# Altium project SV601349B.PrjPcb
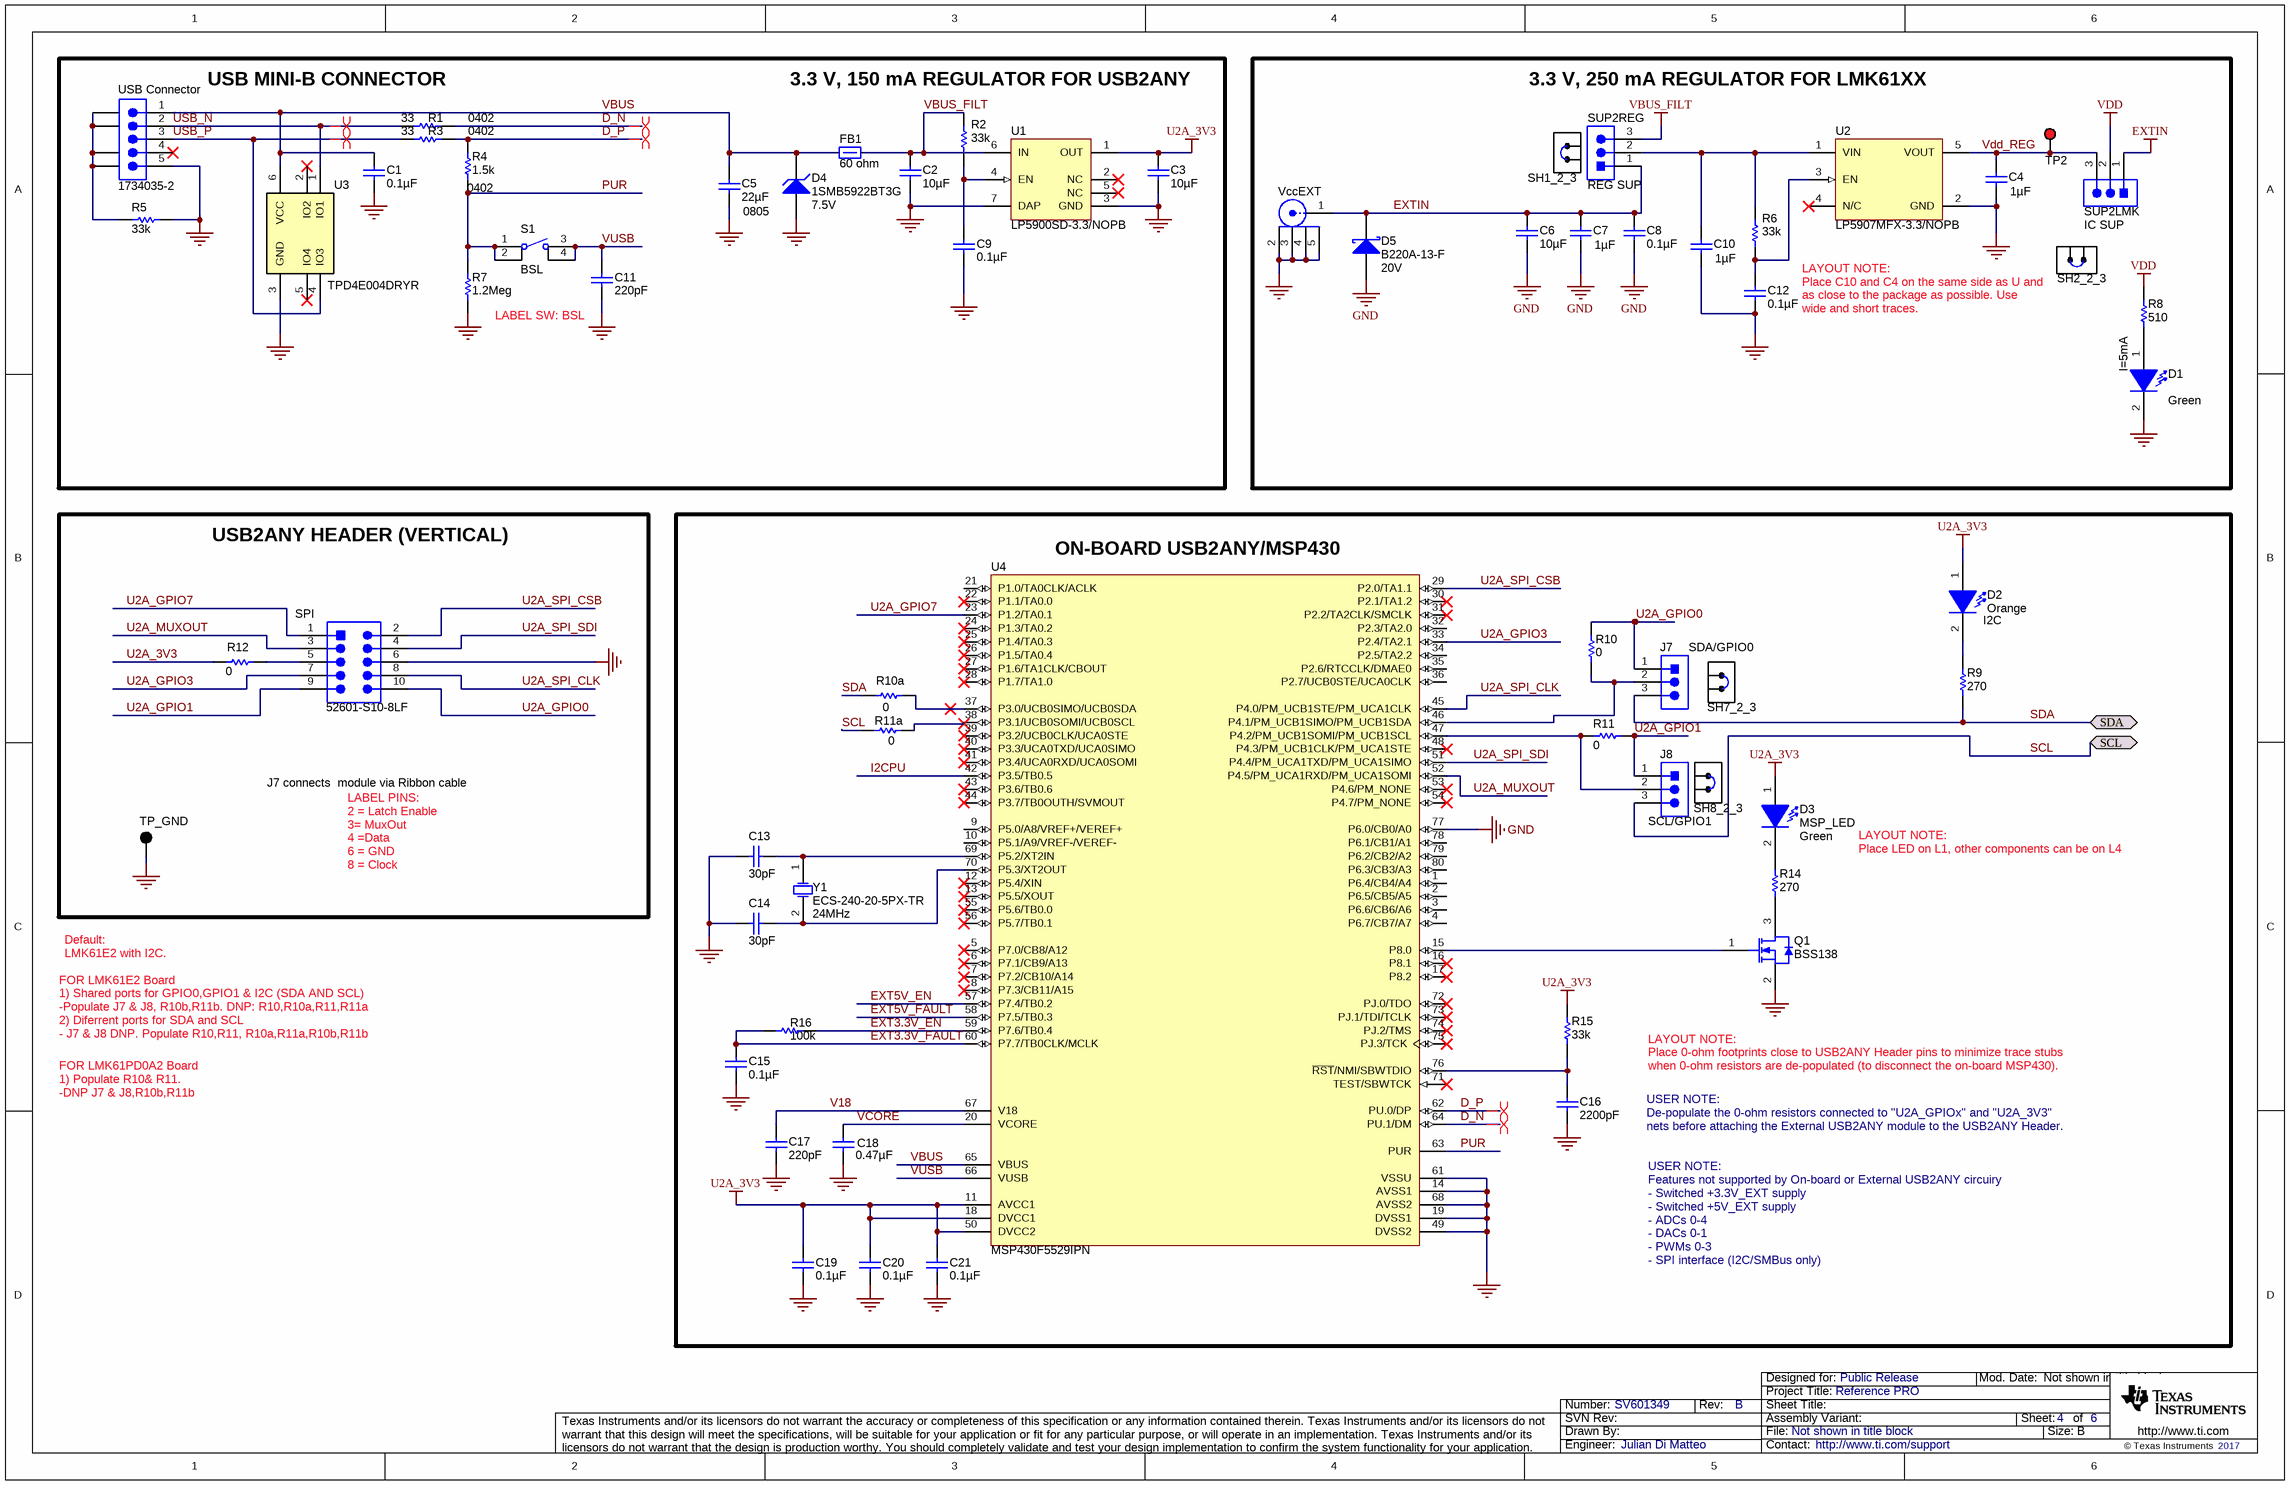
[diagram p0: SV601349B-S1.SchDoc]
CopyrightYear: 2017; PCB_Layout: Julian Di Matteo; PCB_Rev: B; PRJ_Customer: Public Release; PRJ_Engineer: Julian Di Matteo; PRJ_Number: SV601349; PRJ_Title: Reference PRO; SCH_Rev: B; TechSupport: http://www.ti.com/support; TID: N/A
3 sheets, 124 parts. Net scope: flat (ports and power ports of the same name join across sheets).
Board file: SV601349B.PcbDoc
Sheets:
  SV601349B-S1.SchDoc
  SV601349B-S2.SchDoc
  SV601349B-S3.SchDoc

## Sheet SV601349B-S1.SchDoc
size 431 x 279 mm; Date: Not shown in title block; ApprovedBy: Not shown in title block; CheckedBy: Not shown in title block; Author: Julian Di Matteo; CompanyName: Not shown in title block; Engineer: Not shown in title block; Organization: Not shown in title block; Address1: Not shown in title block; Address2: Not shown in title block; Address3: Not shown in title block; Address4: Not shown in title block; DocumentNumber: 4; Revision: Use project parameter SCH_Rev; SheetNumber: 4; SheetTotal: 6; PageSetup: Record=PageOptions¦CenterHorizontal=True¦CenterVertical=True¦PrintScale=0.90¦XCorrection=1.00¦YCorrection=1.00¦PrintKind=0¦BorderSize=5000000¦LeftOffset=0¦BottomOffset=0¦Orientation=2¦PaperLength=1000¦PaperWidth=1000¦Scale=100¦PaperSource=15¦PrintQuality=600¦MediaType=1¦DitherType=10¦PaperKind=Letter (8.5 x 11")¦PrintScaleMode=1; SheetTitle: USB2ANY / Power

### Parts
C1  ValueDisplayed: 0.1µF  [0603]  (hidden comment: C0603C104J4RACTU)
C2  ValueDisplayed: 10µF  [0603]  (hidden comment: C1608X5R1A106M080AC)
C3  ValueDisplayed: 10µF  [0603]  (hidden comment: C1608X5R1A106M080AC)
C4  ValueDisplayed: 1µF  [0603]  (hidden comment: C0603C105K8PACTU)
C5  ValueDisplayed: 22µF  [0805]  (hidden comment: LMK212BJ226MG-T)
C6  ValueDisplayed: 10µF  [0603]  (hidden comment: C1608X5R1A106M080AC)
C7  ValueDisplayed: 1µF  [0603]  (hidden comment: C0603C105K8PACTU)
C8  ValueDisplayed: 0.1µF  [0603]  (hidden comment: C0603C104J4RACTU)
C9  ValueDisplayed: 0.1µF  [0603]  (hidden comment: C0603C104J4RACTU)
C10  ValueDisplayed: 1µF  [0603]  (hidden comment: C0603C105K8PACTU)
C11  ValueDisplayed: 220pF  [0603]  (hidden comment: 06035A221FAT2A)
C12  ValueDisplayed: 0.1µF  [0603]  (hidden comment: C0603C104J4RACTU)
C13  ValueDisplayed: 30pF  [0603M]  (hidden comment: 06035A300JAT2A)
C14  ValueDisplayed: 30pF  [0603M]  (hidden comment: 06035A300JAT2A)
C15  ValueDisplayed: 0.1µF  [0603L]  (hidden comment: C0603C104J4RACTU)
C16  ValueDisplayed: 2200pF  [0603]  (hidden comment: C0603C222K5RACTU)
C17  ValueDisplayed: 220pF  [0603M]  (hidden comment: 06035A221FAT2A)
C18  ValueDisplayed: 0.47µF  [0603M]  (hidden comment: GRM188R71A474KA61D)
C19  ValueDisplayed: 0.1µF  [0603L]  (hidden comment: C0603C104J4RACTU)
C20  ValueDisplayed: 0.1µF  [0603L]  (hidden comment: C0603C104J4RACTU)
C21  ValueDisplayed: 0.1µF  [0603]  (hidden comment: C0603C104J4RACTU)
D1  value Green  [LED_LTST-C190]  (hidden comment: VDD)
D2  I2C  value Orange  [LED_LTST-C190]
D3  MSP_LED  value Green  [LED_LTST-C190]
D4  1SMB5922BT3G  value 7.5V  [SMB]
D5  B220A-13-F  value 20V  [SMA]
FB1  value 60 ohm  [0603]  (hidden comment: MPZ1608S600ATAH0)
J7  SDA/GPIO0  [TSW-103-07-G-S]
J8  SCL/GPIO1  [TSW-103-07-G-S]
Q1  BSS138  [SOT-23]
R1  value 33  [0402]  (hidden comment: CRCW040233R0JNED)
R2  value 33k  [0603]  (hidden comment: CRCW060333K0JNEA)
R3  value 33  [0402]  (hidden comment: CRCW040233R0JNED)
R4  value 1.5k  [0402]  (hidden comment: CRCW04021K50JNED)
R5  value 33k  [0603]  (hidden comment: CRCW060333K0JNEA)
R6  value 33k  [0603L]  (hidden comment: CRCW060333K0JNEA)
R7  value 1.2Meg  [0603]  (hidden comment: CRCW06031M20JNEA)
R8  ValueDisplayed: 510  [0603]  (hidden comment: CRCW0603510RJNEA)
R9  value 270  [0603L]  (hidden comment: CRCW0603270RJNEA)
R10  value 0  [0603L]  (hidden comment: CRCW06030000Z0EA)
R10a  value 0  [0603L]  (hidden comment: CRCW06030000Z0EA)
R11  value 0  [0603L]  (hidden comment: CRCW06030000Z0EA)
R11a  value 0  [0603L]  (hidden comment: CRCW06030000Z0EA)
R12  value 0  [0603L]  (hidden comment: CRCW06030000Z0EA)
R14  value 270  [0603]  (hidden comment: CRCW0603270RJNEA)
R15  value 33k  [0603]  (hidden comment: CRCW060333K0JNEA)
R16  value 100k  [0603L]  (hidden comment: CRCW0603100KJNEA)
S1  BSL  [SW_FSM4JSMA]
SH1_2_3  969102-0000-DA  [SNT-100-BK-G]  (value not drawn)
SH2_2_3  969102-0000-DA  [SNT-100-BK-G]  (value not drawn)
SH7_2_3  969102-0000-DA  [SNT-100-BK-G]  (value not drawn)
SH8_2_3  969102-0000-DA  [SNT-100-BK-G]  (value not drawn)
SPI  52601-S10-8LF  [FCI_52601-S10-8LF]
SUP2LMK  IC SUP  [TSW-103-07-G-S]
SUP2REG  REG SUP  [TSW-103-07-G-S]
TP2  VDD REG  [Keystone5000]  (value not drawn)
TP_GND  GND  [Keystone5001]  (value not drawn)
U1  LP5900SD-3.3/NOPB  [SDB06A]
U2  LP5907MFX-3.3/NOPB  [DBV0005A_N]
U3  TPD4E004DRYR  [DRY0006A]
U4  MSP430F5529IPN  [PN0080A_N]
USB_Connector  1734035-2  [CONN_USB-Mini-B-1734035-2]
VccEXT  (no value)  [Emerson_142-0701-851]
Y1  ECS-240-20-5PX-TR  Frequency: 24MHz  [XTAL_CSM-7X]

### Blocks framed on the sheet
3.3 V, 250 mA REGULATOR FOR LMK61XX: C4 C6-C8 C10 C12 D1 D5 R6 R8 SH1_2_3 SH2_2_3 SUP2LMK SUP2REG TP2 U2 VccEXT
USB2ANY HEADER (VERTICAL): R12 SPI TP_GND
ON-BOARD USB2ANY/MSP430: C13-C21 D2 D3 J7 J8 Q1 R9 R10 R10a R11 R11a R14-R16 SH7_2_3 SH8_2_3 U4 Y1

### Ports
SCL (bidir), SDA (bidir)

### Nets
EXTIN: C6.1 C7.2 C8.2 D5.1(K) SUP2LMK.1 SUP2REG.1 VccEXT.1
GND: C1.1 C2.1 C3.1 C4.1 C5.2 C6.2 C7.1 C8.1 C9.1 C10.1 C11.1 C12.1 C13.2 C14.2 C15.1 C16.2 C17.1 C18.1 C19.1 C20.1 C21.1 D1.2(K) D4.2(A) D5.2(A) Q1.2(S) R5.2 R7.1 SPI.6 TP_GND.1 U1.3(GND) U1.7(DAP) U2.2(GND) U3.3(GND) U4.14(AVSS1) U4.19(DVSS1) U4.49(DVSS2) U4.61(VSSU) U4.68(AVSS2) U4.77(P6.0/CB0/A0) USB_Connector.5 VccEXT.2 VccEXT.3 VccEXT.4 VccEXT.5
U2A_3V3: C3.2 C19.2 C20.2 C21.2 D2.1(A) D3.1(A) R12.1 R15.1 U1.1(OUT) U4.11(AVCC1) U4.18(DVCC1) U4.50(DVCC2)
VBUS_FILT: C2.2 FB1.2 R2.1 SUP2REG.3 U1.6(IN)
VDD: R8.2 SUP2LMK.2
D_N: R1.1 U4.64(PU.1/DM)
D_P: R3.1 R4.2 U4.62(PU.0/DP)
EXT3.3V_EN: R16.2 U4.59(P7.6/TB0.4)
EXT3.3V_FAULT: C15.2 R16.1 U4.60(P7.7/TB0CLK/MCLK)
EXT5V_EN: U4.57(P7.4/TB0.2)
EXT5V_FAULT: U4.58(P7.5/TB0.3)
I2CPU: U4.42(P3.5/TB0.5)
PUR: R4.1 R7.2 S1.1 S1.2 U4.63(PUR)
SCL: J8.3 R11a.2 ; port SCL
SDA: J7.3 R9.1 R10a.2 ; port SDA
U2A_GPIO0: J7.1 R10.2 SPI.10
U2A_GPIO1: J8.1 R11.1 SPI.9
U2A_GPIO3: SPI.7 U4.33(P2.4/TA2.1)
U2A_GPIO7: SPI.1 U4.23(P1.2/TA0.1)
U2A_MUXOUT: SPI.3 U4.52(P4.5/PM_UCA1RXD/PM_UCA1SOMI)
U2A_SPI_CLK: SPI.8 U4.45(P4.0/PM_UCB1STE/PM_UCA1CLK)
U2A_SPI_CSB: SPI.2 U4.29(P2.0/TA1.1)
U2A_SPI_SDI: SPI.4 U4.51(P4.4/PM_UCA1TXD/PM_UCA1SIMO)
USB_N: R1.2 U3.1(IO1) USB_Connector.2
USB_P: R3.2 U3.4(IO3) USB_Connector.3
V18: C17.2 U4.67(V18)
VBUS: C1.2 C5.1 D4.1(K) FB1.1 U3.6(VCC) U4.65(VBUS) USB_Connector.1
VCORE: C18.2 U4.20(VCORE)
Vdd_REG: C4.2 SUP2LMK.3 TP2.1 U2.5(VOUT)
VUSB: C11.2 S1.3 S1.4 U4.66(VUSB)
NetC9_2: C9.2 R2.2 U1.4(EN)
NetC10_2: C10.2 R6.1 SUP2REG.2 U2.1(VIN)
NetC12_2: C12.2 R6.2 U2.3(EN)
NetC13_1: C13.1 U4.69(P5.2/XT2IN) Y1.1(OSC1)
NetC14_1: C14.1 U4.70(P5.3/XT2OUT) Y1.2(OSC2)
NetC16_1: C16.1 R15.2 U4.76(~{RST}/NMI/SBWTDIO)
NetD1_1: D1.1(A) R8.1
NetD2_2: D2.2(K) R9.2
NetD3_2: D3.2(K) R14.2
NetJ7_2: J7.2 R10.1 U4.46(P4.1/PM_UCB1SIMO/PM_UCB1SDA)
NetJ8_2: J8.2 R11.2 U4.47(P4.2/PM_UCB1SOMI/PM_UCB1SCL)
NetQ1_1: Q1.1(G) U4.15(P8.0)
NetQ1_3: Q1.3(D) R14.1
NetR5_1: R5.1 USB_Connector.6(GND) USB_Connector.7(GND) USB_Connector.8(GND) USB_Connector.9(GND)
NetR10a_1: R10a.1 U4.37(P3.0/UCB0SIMO/UCB0SDA)
NetR11a_1: R11a.1 U4.38(P3.1/UCB0SOMI/UCB0SCL)
NetR12_2: R12.2 SPI.5

Not connected (* = marked no-connect by the designer): U1 2(NC)* 5(NC)*; U2 4(N/C)*; U3 2(IO2)* 5(IO4)*; U4 1(P6.4/CB4/A4) 2(P6.5/CB5/A5) 3(P6.6/CB6/A6) 4(P6.7/CB7/A7) 5(P7.0/CB8/A12)* 6(P7.1/CB9/A13)* 7(P7.2/CB10/A14)* 8(P7.3/CB11/A15)* 9(P5.0/A8/VREF+/VEREF+) 10(P5.1/A9/VREF-/VEREF-) 12(P5.4/XIN)* 13(P5.5/XOUT)* 16(P8.1)* 17(P8.2)* 21(P1.0/TA0CLK/ACLK) 22(P1.1/TA0.0)* 24(P1.3/TA0.2)* 25(P1.4/TA0.3)* 26(P1.5/TA0.4)* 27(P1.6/TA1CLK/CBOUT)* 28(P1.7/TA1.0)* 30(P2.1/TA1.2)* 31(P2.2/TA2CLK/SMCLK)* 32(P2.3/TA2.0) 34(P2.5/TA2.2) 35(P2.6/RTCCLK/DMAE0) 36(P2.7/UCB0STE/UCA0CLK) 39(P3.2/UCB0CLK/UCA0STE)* 40(P3.3/UCA0TXD/UCA0SIMO)* 41(P3.4/UCA0RXD/UCA0SOMI)* 43(P3.6/TB0.6)* 44(P3.7/TB0OUTH/SVMOUT)* 48(P4.3/PM_UCB1CLK/PM_UCA1STE)* 53(P4.6/PM_NONE)* 54(P4.7/PM_NONE)* 55(P5.6/TB0.0)* 56(P5.7/TB0.1)* 71(TEST/SBWTCK)* 72(PJ.0/TDO)* 73(PJ.1/TDI/TCLK)* 74(PJ.2/TMS)* 75(PJ.3/TCK)* 78(P6.1/CB1/A1) 79(P6.2/CB2/A2) 80(P6.3/CB3/A3); USB_Connector 4*

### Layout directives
differential pair: D_N, D_P, USB_N, USB_P

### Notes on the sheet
- USB MINI-B CONNECTOR
- (near R2) 3.3 V, 150 mA REGULATOR FOR USB2ANY
- LABEL SW: BSL
- (near SH2_2_3) LAYOUT NOTE:
  Place C10 and C4 on the same side as U and as close to the package as possible. Use wide and short traces.
- I=5mA
- J7 connects  module via Ribbon cable
- LAYOUT NOTE:
  Place LED on L1, other components can be on L4
- LABEL PINS:
  2 = Latch Enable
  3= MuxOut
  4 =Data
  6 = GND
  8 = Clock
- Default:
  LMK61E2 with I2C.
- FOR LMK61E2 Board
  1) Shared ports for GPIO0,GPIO1 & I2C (SDA AND SCL)
  -Populate J7 & J8, R10b,R11b. DNP: R10,R10a,R11,R11a
  2) Diferrent ports for SDA and SCL
  - J7 & J8 DNP. Populate R10,R11, R10a,R11a,R10b,R11b
- LAYOUT NOTE:
  Place 0-ohm footprints close to USB2ANY Header pins to minimize trace stubs when 0-ohm resistors are de-populated (to disconnect the on-board MSP430).
- FOR LMK61PD0A2 Board
  1) Populate R10& R11.
  -DNP J7 & J8,R10b,R11b
- USER NOTE:
  De-populate the 0-ohm resistors connected to "U2A_GPIOx" and "U2A_3V3" nets before attaching the External USB2ANY module to the USB2ANY Header.
- USER NOTE:
  Features not supported by On-board or External USB2ANY circuiry
  - Switched +3.3V_EXT supply
  - Switched +5V_EXT supply
  - ADCs 0-4
  - DACs 0-1
  - PWMs 0-3
  - SPI interface (I2C/SMBus only)

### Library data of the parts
C1 C8 C9 C12 C21 = C0603C104J4RACTU: CAP, CERM, 0.1uF, 16V, +/-5%, X7R, 0603; Manufacturer: Kemet; Polarized: N; CompType: Capacitor; U/M: EA; Cap_F: 0.0000001; Tolerance_%: 5; Value1: Unknown; VDC_V: 16; TaMin_C: -55; TaMax_C: 125
C2 C3 = C1608X5R1A106M080AC: CAP, CERM, 10 µF, 10 V, +/- 20%, X5R, 0603; Manufacturer: TDK; ESR_ohm: 0.0078; IRMS_A: 1.85; Polarized: N; TaMax_C: 85; TaMin_C: -55; Tolerance_%: 20; VDC_V: 10; Cap_F: 0.00001; CompType: Capacitor; Value: 10uF; Value1: 0.0078 ohm; Value2: 10V; U/M: EA; SizeArea_mm2: 1.28; SizeAreaWB_mm2: 4.68; SizeX_mm: 1.6; SizeY_mm: 0.8; SizeZ_mm: 1; AEC Category: Q200
C4 C7 C10 = C0603C105K8PACTU: CAP, CERM, 1uF, 10V, +/-10%, X5R, 0603; Manufacturer: Kemet; Polarized: N; TaMax_C: 85; TaMin_C: -55; Tolerance_%: 10; Cap_F: 1.0E-6; CompType: Capacitor
C5 = LMK212BJ226MG-T: CAP, CERM, 22uF, 10V, +/-20%, X5R, 0805; Manufacturer: Taiyo Yuden; Polarized: N; CompType: Capacitor; U/M: EA; Cap_F: 0.000022; Tolerance_%: 20; Value1: Unknown; VDC_V: 10; TaMin_C: -55; TaMax_C: 85
C6 = C1608X5R1A106M080AC: CAP, CERM, 10 µF, 10 V, +/- 20%, X5R, 0603; Manufacturer: TDK; Polarized: N; CompType: Capacitor; Value: 10uF; U/M: EA; Cap_F: 0.00001; Tolerance_%: 20; ESR_ohm: 0.0078; Value1: 0.0078 ohm; VDC_V: 10; Value2: 10V; IRMS_A: 1.85; TaMin_C: -55; TaMax_C: 85; SizeArea_mm2: 1.28; SizeAreaWB_mm2: 4.68; SizeX_mm: 1.6; SizeY_mm: 0.8; SizeZ_mm: 1; AEC Category: Q200
C11 = 06035A221FAT2A: CAP, CERM, 220pF, 50V, +/-1%, C0G/NP0, 0603; Manufacturer: AVX; Polarized: N; CompType: Capacitor; U/M: EA; Cap_F: 0.00000000022; Tolerance_%: 1; ESR_Ohm: 0.083; Value1: 0.083 ohm; VDC_V: 50; TaMin_C: -55; TaMax_C: 125
C13 C14 = 06035A300JAT2A: CAP, CERM, 30 pF, 50 V, +/- 5%, C0G/NP0, 0603; Manufacturer: AVX; Polarized: N; CompType: Capacitor; Value: 30pF; U/M: EA; Cap_F: 0.00000000003; Tolerance_%: 5; ESR_ohm: 0.232; Value1: 0.232 ohm; VDC_V: 50; Value2: 50V; TaMin_C: -55; TaMax_C: 125; Cap_Case: 0603
C15 C19 C20 = C0603C104J4RACTU: CAP, CERM, 0.1uF, 16V, +/-5%, X7R, 0603; Manufacturer: Kemet; Polarized: N; CompType: Capacitor; U/M: EA; Cap_F: 0.0000001; Tolerance_%: 5; Value1: Unknown; VDC_V: 16; TaMin_C: -55; TaMax_C: 125; Cap_Case: 0603
C16 = C0603C222K5RACTU: CAP, CERM, 2200pF, 50V, +/-10%, X7R, 0603; Manufacturer: Kemet; Polarized: N; CompType: Capacitor; U/M: EA; Cap_F: 0.0000000022; Tolerance_%: 10; Value1: Unknown; VDC_V: 50; TaMin_C: -55; TaMax_C: 125
C17 = 06035A221FAT2A: CAP, CERM, 220pF, 50V, +/-1%, C0G/NP0, 0603; Manufacturer: AVX; Polarized: N; CompType: Capacitor; U/M: EA; Cap_F: 0.00000000022; Tolerance_%: 1; ESR_Ohm: 0.083; Value1: 0.083 ohm; VDC_V: 50; TaMin_C: -55; TaMax_C: 125; Cap_Case: 0603
C18 = GRM188R71A474KA61D: CAP, CERM, 0.47uF, 10V, +/-10%, X7R, 0603; Manufacturer: MuRata; Polarized: N; CompType: Capacitor; U/M: EA; Cap_F: 0.00000047; Tolerance_%: 10; TaMin_C: -55; TaMax_C: 125; Cap_Case: 0603
D1 D3 = LTST-C190GKT: LED, Green, SMD; Manufacturer: Lite-On; Vf_V: 2.1; Value2: 2.1V; Io_A: 0.02; Power_TotalModule: 0.1; Value1: 0.1W; U/M: EA
D2 = LTST-C190KFKT: LED, Orange, SMD; Manufacturer: Lite-On; Type: AlInGaP; Vf_V: 2; Value2: 2V; Io_A: 0.02; Power_TotalModule: 0.075; Value1: 0.075W; U/M: EA
D4 = 1SMB5922BT3G: Diode, Zener, 7.5V, 550mW, SMB; Manufacturer: ON Semiconductor; SymbolCreator: a0412235; U/M: EA; Power_W: 0.55; Vz_V: 7.5; Value1: 0.55W; RJA_CperW: 226
D5 = B220A-13-F: Diode, Schottky, 20V, 2A, SMA; Manufacturer: Diodes Inc.; U/M: EA; Vf_V: 0.5; Value2: 0.5V; Io_A: 2; Vr_V: 20; TJmax_C: 150
FB1 = MPZ1608S600ATAH0: Ferrite Bead, 60 ohm @ 100 MHz, 3.5 A, 0603; Manufacturer: TDK; Imax_A: 3.5; DCR_ohm: 0.02; Value1: 0.02 ohm; Value2: 3.5A; ZTyp@100MHz_Ohm: 60; SizeAreaWB_mm2: 4.68; SizeArea_mm2: 1.28; SizeX_mm: 1.6; SizeY_mm: 0.8; SizeZ_mm: 1
J7 J8 SUP2LMK SUP2REG = TSW-103-07-G-S: Header, 100mil, 3x1, Gold, TH; Manufacturer: Samtec; SymbolCreator: a0799628; U/M: EA
Q1 = BSS138: MOSFET, N-CH, 50V, 0.22A, SOT-23; Manufacturer: Fairchild Semiconductor; Alternate Manufacturer: None; U/M: EA; ChType: N; VdsMax_V: 50; Value1: 6 ohm; Rdson45_Ohm: 6; Value2: 1.7 nC; QgTyp_nC: 1.7; Vgs_V: 20; IdsMax_A: 0.22
R1 R3 = CRCW040233R0JNED: RES, 33 ohm, 5%, 0.063W, 0402; Manufacturer: Vishay-Dale; CompType: Resistor; Value_Code: 33R0; Tolerance_%: 5; Power_W: 0.063; VDC_V: 50; TempCo: 200 ppm/C; EIA_Code: E24; U/M: EA
R2 R5 R6 R15 = CRCW060333K0JNEA: RES, 33k ohm, 5%, 0.1W, 0603; Manufacturer: Vishay-Dale; CompType: Resistor; Res_ohm: 33000; Value_Code: 33k0; Tolerance_%: 5; Power_W: 0.1; VDC_V: 75; TempCo: 200 ppm/C; EIA_Code: E24; U/M: EA
R4 = CRCW04021K50JNED: RES, 1.5k ohm, 5%, 0.063W, 0402; Manufacturer: Vishay-Dale; CompType: Resistor; Res_ohm: 1500; Value_Code: 1k50; Tolerance_%: 5; Power_W: 0.063; VDC_V: 50; TempCo: 200 ppm/C; EIA_Code: E24; U/M: EA
R7 = CRCW06031M20JNEA: RES, 1.2Meg ohm, 5%, 0.1W, 0603; Manufacturer: Vishay-Dale; CompType: Resistor; Res_ohm: 1200000; Value_Code: 1M20; Tolerance_%: 5; Power_W: 0.1; VDC_V: 75; TempCo: 200 ppm/C; EIA_Code: E24; U/M: EA
R8 = CRCW0603510RJNEA: RES, 510, 5%, 0.1 W, 0603; Manufacturer: Vishay-Dale; CompType: Resistor; Value: 510; Value_Code: 510R; Tolerance_%: 5; Power_W: 0.1; Value2: 0.1W; VDC_V: 75; TempCo: 200 ppm/C; EIA_Code: E24; U/M: EA
R9 R14 = CRCW0603270RJNEA: RES, 270 ohm, 5%, 0.1W, 0603; Manufacturer: Vishay-Dale; CompType: Resistor; Value_Code: 270R; Tolerance_%: 5; Power_W: 0.1; VDC_V: 75; TempCo: 200 ppm/C; EIA_Code: E24; U/M: EA
R10 R10a R11 R11a R12 = CRCW06030000Z0EA: RES, 0 ohm, 5%, 0.1W, 0603; Manufacturer: Vishay-Dale; CompType: Resistor; Value_Code: 0000; Tolerance_%: 5; Power_W: 0.1; VDC_V: 75; TempCo: 200 ppm/C; EIA_Code: E24; U/M: EA
R16 = CRCW0603100KJNEA: RES, 100k ohm, 5%, 0.1W, 0603; Manufacturer: Vishay-Dale; CompType: Resistor; Res_ohm: 100000; Tolerance_%: 5; Power_W: 0.1; VDC_V: 75; TempCo: 200 ppm/C; EIA_Code: E24; U/M: EA
S1 = 4-1437565-1: Switch, Tactile, SPST-NO, 0.05A, 12V, SMT; Manufacturer: TE Connectivity; SymbolCreator: a0412235; VDC_V: 12; SwitchFunction: Off-Mom; PositionCount: 1; CurrentRating_mA: 50
SH1_2_3 SH2_2_3 SH7_2_3 SH8_2_3 = 969102-0000-DA: Shunt, 100mil, Gold plated, Black; Manufacturer: 3M; Alternate Manufacturer: Samtec; Value: 1x2; Note: You can "mate" this to a header by matching the designator.  i.e. use SH-J3 for header J3
SPI = 52601-S10-8LF: Header (shrouded), 100mil, 5x2, Gold, SMT; Manufacturer: FCI; SymbolCreator: a0412235
TP2 = 5000: Test Point, Miniature, Red, TH; Manufacturer: Keystone; CompType: Test Point Loop; U/M: EA
TP_GND = 5001: Test Point, Miniature, Black, TH; Manufacturer: Keystone; CompType: Test Point Loop; U/M: EA
U1 = LP5900SD-3.3/NOPB: Ultra Low Noise, 150mA Linear Regulator for RF/Analog Circuits Requires No Bypass Capacitor, 6-pin LLP, Pb-Free; Manufacturer: Texas Instruments; PackageTopMarking: XTT*L16; PowerWise: N; CompType: LDO IC
U2 = LP5907MFX-3.3/NOPB: ULTRA LOW-NOISE, 250-mA LINEAR REGULATOR FOR RF AND ANALOG CIRCUITS REQUIRES NO BYPASS CAPACITOR, DBV0005A; Manufacturer: Texas Instruments; SymbolCreator: a0799628; CompType: IC; U/M: EA
U3 = TPD4E004DRYR: ESD-Protection Array for High-Speed Data Interfaces, 4 Channels, -40 to +85 degC, 6-pin SON (DRY), Green (RoHS & no Sb/Br); Manufacturer: Texas Instruments; Alternate PartNumber: Equivalent; 1394 / Firewire: TRUE; Breakdown Voltage(Min)(V): 6; IEC 61000-4-2 Air-Gap(+/- kV): 12; IEC 61000-4-2 Contact(+/- kV): 8; IO Capacitance(Typ)(pF): 1.6; IO Leakage Current(nA): 1; SubFamily: ESD Solution
U4 = MSP430F5529IPN: Mixed Signal MicroController, PN0080A; Alternate Manufacturer: None; Manufacturer: Texas Instruments; ADC: 12-bit SAR; ADC Channels: 16; Brown Out Reset: Yes; DMA: 3; Eco-Plan: Green (RoHS & no Sb/Br); Flash(KB): 128; Frequency(MHz): 25; GPIO: 63; Multiplier: 32x32; SRAM(B): 8192; SubFamily: 5 Series; Timers - 16-bit: 4; USB: 1; USCI_A (UART/LIN/IrDA/SPI): 2; SymbolCreator: Altium/a0412235; CompType: IC; U/M: EA
USB_Connector = 1734035-2: Connector, Receptacle, Mini-USB Type B, R/A, Top Mount SMT; Manufacturer: TE Connectivity; SymbolCreator: A0412235; U/M: EA
VccEXT = 142-0701-851: Connector, End launch SMA, 50 ohm, SMT; Manufacturer: Emerson Network Power; SymbolCreator: X0208326; U/M: EA
Y1 = ECS-240-20-5PX-TR: Crystal, 24.000MHz, 20pF, SMD; Manufacturer: ECS Inc.; SymbolCreator: a0412235; U/M: EA; TaMin_C: -10; TaMax_C: 70; Frequency Stability: ±50ppm

## Sheet SV601349B-S2.SchDoc: DUT
size 431 x 279 mm; Date: Not shown in title block; ApprovedBy: Not shown in title block; CheckedBy: Not shown in title block; Author: Not shown in title block; CompanyName: Not shown in title block; DrawnBy: Not shown in title block; Engineer: Not shown in title block; Organization: Not shown in title block; Address1: Not shown in title block; Address2: Not shown in title block; Address3: Not shown in title block; Address4: Not shown in title block; DocumentNumber: 3; Revision: Use project parameter SCH_Rev; SheetNumber: 3; SheetTotal: 6; PageSetup: Record=PageOptions¦CenterHorizontal=True¦CenterVertical=True¦PrintScale=1.00¦XCorrection=1.00¦YCorrection=1.00¦PrintKind=0¦BorderSize=5000000¦LeftOffset=0¦BottomOffset=0¦Orientation=2¦PaperLength=1000¦PaperWidth=1000¦Scale=100¦PaperSource=15¦PrintQuality=600¦MediaType=1¦DitherType=10¦PaperKind=Letter¦PrintScaleMode=1
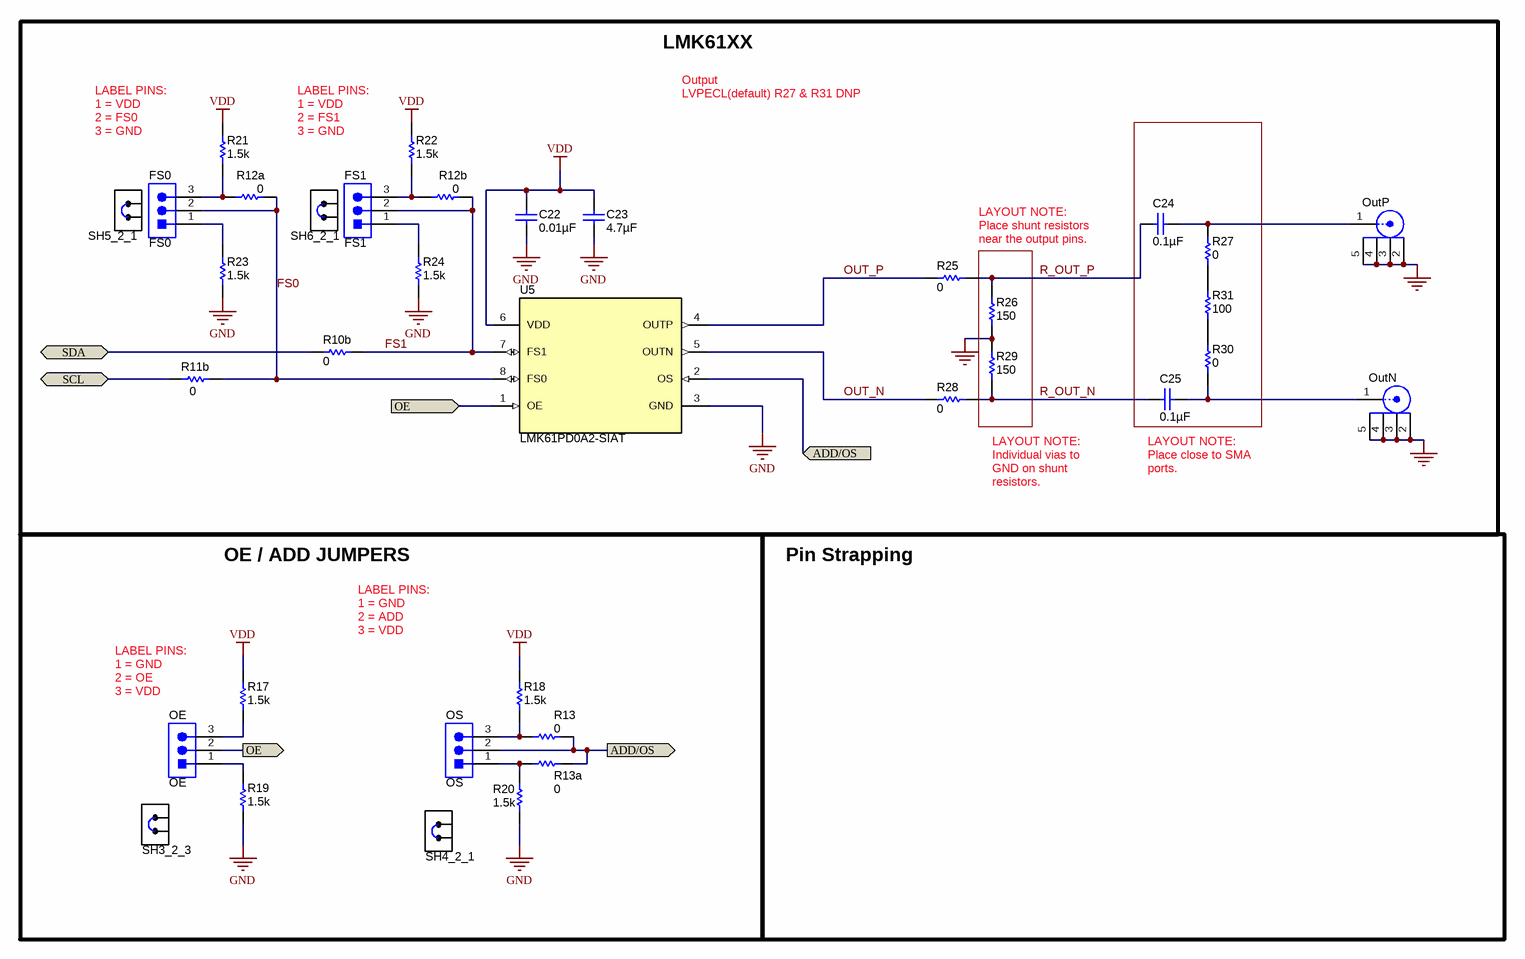
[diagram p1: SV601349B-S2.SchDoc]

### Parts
C22  ValueDisplayed: 0.01µF  [0603]  (hidden comment: 06031C103JAT2A)
C23  ValueDisplayed: 4.7µF  [0603]  (hidden comment: C0603C475K8PACTU)
C24  ValueDisplayed: 0.1µF  [0603L]  (hidden comment: C0603C104J4RACTU)
C25  ValueDisplayed: 0.1µF  [0603L]  (hidden comment: C0603C104J4RACTU)
FS0  FS0  [TE_5-146278-3]
FS1  FS1  [TE_5-146278-3]
OE  OE  [TSW-103-07-G-S]
OS  OS  [TSW-103-07-G-S]
OutN  (no value)  [Emerson_142-0701-851]
OutP  (no value)  [Emerson_142-0701-851]
R10b  value 0  [0603L]  (hidden comment: CRCW06030000Z0EA)
R11b  value 0  [0603L]  (hidden comment: CRCW06030000Z0EA)
R12a  value 0  [0603L]  (hidden comment: CRCW06030000Z0EA)
R12b  value 0  [0603L]  (hidden comment: CRCW06030000Z0EA)
R13  value 0  [0603L]  (hidden comment: CRCW06030000Z0EA)
R13a  value 0  [0603L]  (hidden comment: CRCW06030000Z0EA)
R17  value 1.5k  [0603]  (hidden comment: CRCW06031K50JNEA)
R18  value 1.5k  [0603]  (hidden comment: CRCW06031K50JNEA)
R19  value 1.5k  [0603]  (hidden comment: CRCW06031K50JNEA)
R20  value 1.5k  [0603]  (hidden comment: CRCW06031K50JNEA)
R21  value 1.5k  [0603]  (hidden comment: CRCW06031K50JNEA)
R22  value 1.5k  [0603]  (hidden comment: CRCW06031K50JNEA)
R23  value 1.5k  [0603]  (hidden comment: CRCW06031K50JNEA)
R24  value 1.5k  [0603]  (hidden comment: CRCW06031K50JNEA)
R25  value 0  [0603L]  (hidden comment: CRCW06030000Z0EA)
R26  ValueDisplayed: 150  [0603L]  (hidden comment: CRCW0603150RJNEA)
R27  value 0  [0603L]  (hidden comment: CRCW06030000Z0EA)
R28  value 0  [0603L]  (hidden comment: CRCW06030000Z0EA)
R29  ValueDisplayed: 150  [0603L]  (hidden comment: CRCW0603150RJNEA)
R30  value 0  [0603L]  (hidden comment: CRCW06030000Z0EA)
R31  ValueDisplayed: 100  [0603L]  (hidden comment: CRCW0603100RFKEA)
SH3_2_3  969102-0000-DA  [SNT-100-BK-G]  (value not drawn)
SH4_2_1  969102-0000-DA  [SNT-100-BK-G]  (value not drawn)
SH5_2_1  969102-0000-DA  [SNT-100-BK-G]  (value not drawn)
SH6_2_1  969102-0000-DA  [SNT-100-BK-G]  (value not drawn)
U5  LMK61PD0A2-SIAT  [SIA0008B]

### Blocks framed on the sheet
LMK61XX: C22-C25 FS0 FS1 OutN OutP R10b R11b R12a R12b R21-R31 SH5_2_1 SH6_2_1 U5
OE / ADD JUMPERS: OE OS R13 R13a R17-R20 SH3_2_3 SH4_2_1

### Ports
ADD/OS (in), ADD/OS (out), OE (in), OE (out), SCL (bidir), SDA (bidir)

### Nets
GND: C22.2 C23.2 OutN.2 OutN.3 OutN.4 OutN.5 OutP.2 OutP.3 OutP.4 OutP.5 R19.2 R20.2 R23.2 R24.2 R26.1 R29.2 U5.3(GND)
VDD: C22.1 C23.1 R17.1 R18.1 R21.1 R22.1 U5.6(VDD)
ADD/OS: OS.2 R13.1 R13a.1 U5.2(OS) ; port ADD/OS
FS0: FS0.2 R11b.2 R12a.1 U5.8(FS0)
FS1: FS1.2 R10b.2 R12b.1 U5.7(FS1)
OE: OE.2 U5.1(OE) ; port OE
OUT_N: R28.1 U5.5(OUTN)
OUT_P: R25.1 U5.4(OUTP)
R_OUT_N: C25.2 R28.2 R29.1
R_OUT_P: C24.2 R25.2 R26.2
SCL: R11b.1 ; port SCL
SDA: R10b.1 ; port SDA
NetC24_1: C24.1 OutP.1 R27.2
NetC25_1: C25.1 OutN.1 R30.1
NetFS0_1: FS0.1 R23.1
NetFS0_3: FS0.3 R12a.2 R21.2
NetFS1_1: FS1.1 R24.1
NetFS1_3: FS1.3 R12b.2 R22.2
NetOE_1: OE.1 R19.1
NetOE_3: OE.3 R17.2
NetOS_1: OS.1 R13a.2 R20.1
NetOS_3: OS.3 R13.2 R18.2
NetR27_1: R27.1 R31.2
NetR30_2: R30.2 R31.1

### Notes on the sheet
- LABEL PINS:
  1 = VDD
  2 = FS0
  3 = GND
- (near R22) LABEL PINS:
  1 = VDD
  2 = FS1
  3 = GND
- Output
  LVPECL(default) R27 & R31 DNP
- LAYOUT NOTE:
  Place shunt resistors near the output pins.
- LAYOUT NOTE:
  Individual vias to GND on shunt resistors.
- (near C25) LAYOUT NOTE:
  Place close to SMA ports.
- Pin Strapping
- LABEL PINS:
  1 = GND
  2 = ADD
  3 = VDD
- LABEL PINS:
  1 = GND
  2 = OE
  3 = VDD

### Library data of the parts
C22 = 06031C103JAT2A: CAP, CERM, 0.01 µF, 100 V, +/- 5%, X7R, 0603; Manufacturer: AVX; Polarized: N; CompType: Capacitor; Value: 0.01uF; U/M: EA; Cap_F: 0.00000001; Tolerance_%: 5; ESR_ohm: 0.098; Value1: 0.098 ohm; VDC_V: 100; Value2: 100V; TaMin_C: -55; TaMax_C: 125
C23 = C0603C475K8PACTU: CAP, CERM, 4.7 µF, 10 V, +/- 10%, X5R, 0603; Manufacturer: Kemet; Polarized: N; CompType: Capacitor; Value: 4.7uF; U/M: EA; Cap_F: 0.0000047; Tolerance_%: 10; ESR_ohm: 0.006; Value1: 0.006 ohm; Value2: 10V; IRMS_A: 7.24; TaMin_C: -55; TaMax_C: 85
C24 C25 = C0603C104J4RACTU: as C15 on sheet SV601349B-S1
FS0 FS1 = 5-146278-3: Header, 100mil, 3x1, Tin, TH; Manufacturer: TE Connectivity; SymbolCreator: a0799628; U/M: EA
OE OS = TSW-103-07-G-S: as J7 on sheet SV601349B-S1
OutN OutP = 142-0701-851: as VccEXT on sheet SV601349B-S1
R10b R11b R12a R12b R13 R13a R25 R27 R28 R30 = CRCW06030000Z0EA: as R10 on sheet SV601349B-S1
R17-R24 = CRCW06031K50JNEA: RES, 1.5k ohm, 5%, 0.1W, 0603; Manufacturer: Vishay-Dale; CompType: Resistor; Res_ohm: 1500; Value_Code: 1k50; Tolerance_%: 5; Power_W: 0.1; VDC_V: 75; TempCo: 200 ppm/C; EIA_Code: E24; U/M: EA
R26 R29 = CRCW0603150RJNEA: RES, 150, 5%, 0.1 W, 0603; Manufacturer: Vishay-Dale; CompType: Resistor; Value: 150; Value_Code: 150R; Tolerance_%: 5; Power_W: 0.1; Value2: 0.1W; VDC_V: 75; TempCo: 200 ppm/C; EIA_Code: E24; U/M: EA
R31 = CRCW0603100RFKEA: RES, 100, 1%, 0.1 W, 0603; Manufacturer: Vishay-Dale; CompType: Resistor; Value: 100; Value_Code: 100R; Tolerance_%: 1; Power_W: 0.1; Value2: 0.1W; VDC_V: 75; TempCo: 100 ppm/C; EIA_Code: E96; U/M: EA
SH3_2_3 SH4_2_1 SH5_2_1 SH6_2_1 = 969102-0000-DA: as SH1_2_3 on sheet SV601349B-S1
U5 = CMP-0075886-1: Ultra-Low Jitter Pin Selectable, Differential Oscillator, +/-50ppm, SIA0008B (QFM-8); Manufacturer: Texas Instruments; SizeArea_mm2: 12.25; SizeAreaWB_mm2: 20.25; SizeX_mm: 3.5; SizeZ_mm: 2.0; CompType: IC; U/M: EA

## Sheet SV601349B-S3.SchDoc
size 431 x 279 mm; Date: Not shown in title block; ApprovedBy: Not shown in title block; CheckedBy: Not shown in title block; Author: Not shown in title block; CompanyName: Not shown in title block; Engineer: Not shown in title block; Organization: Not shown in title block; Address1: Not shown in title block; Address2: Not shown in title block; Address3: Not shown in title block; Address4: Not shown in title block; DocumentNumber: 1; Revision: Use project parameter SCH_Rev; SheetNumber: 1; SheetTotal: 3; PageSetup: Record=PageOptions¦CenterHorizontal=True¦CenterVertical=True¦PrintScale=1.00¦XCorrection=1.00¦YCorrection=1.00¦PrintKind=0¦BorderSize=5000000¦LeftOffset=0¦BottomOffset=0¦Orientation=2¦PaperLength=1000¦PaperWidth=1000¦Scale=100¦PaperSource=15¦PrintQuality=600¦MediaType=1¦DitherType=10¦PaperKind=Letter¦PrintScaleMode=1
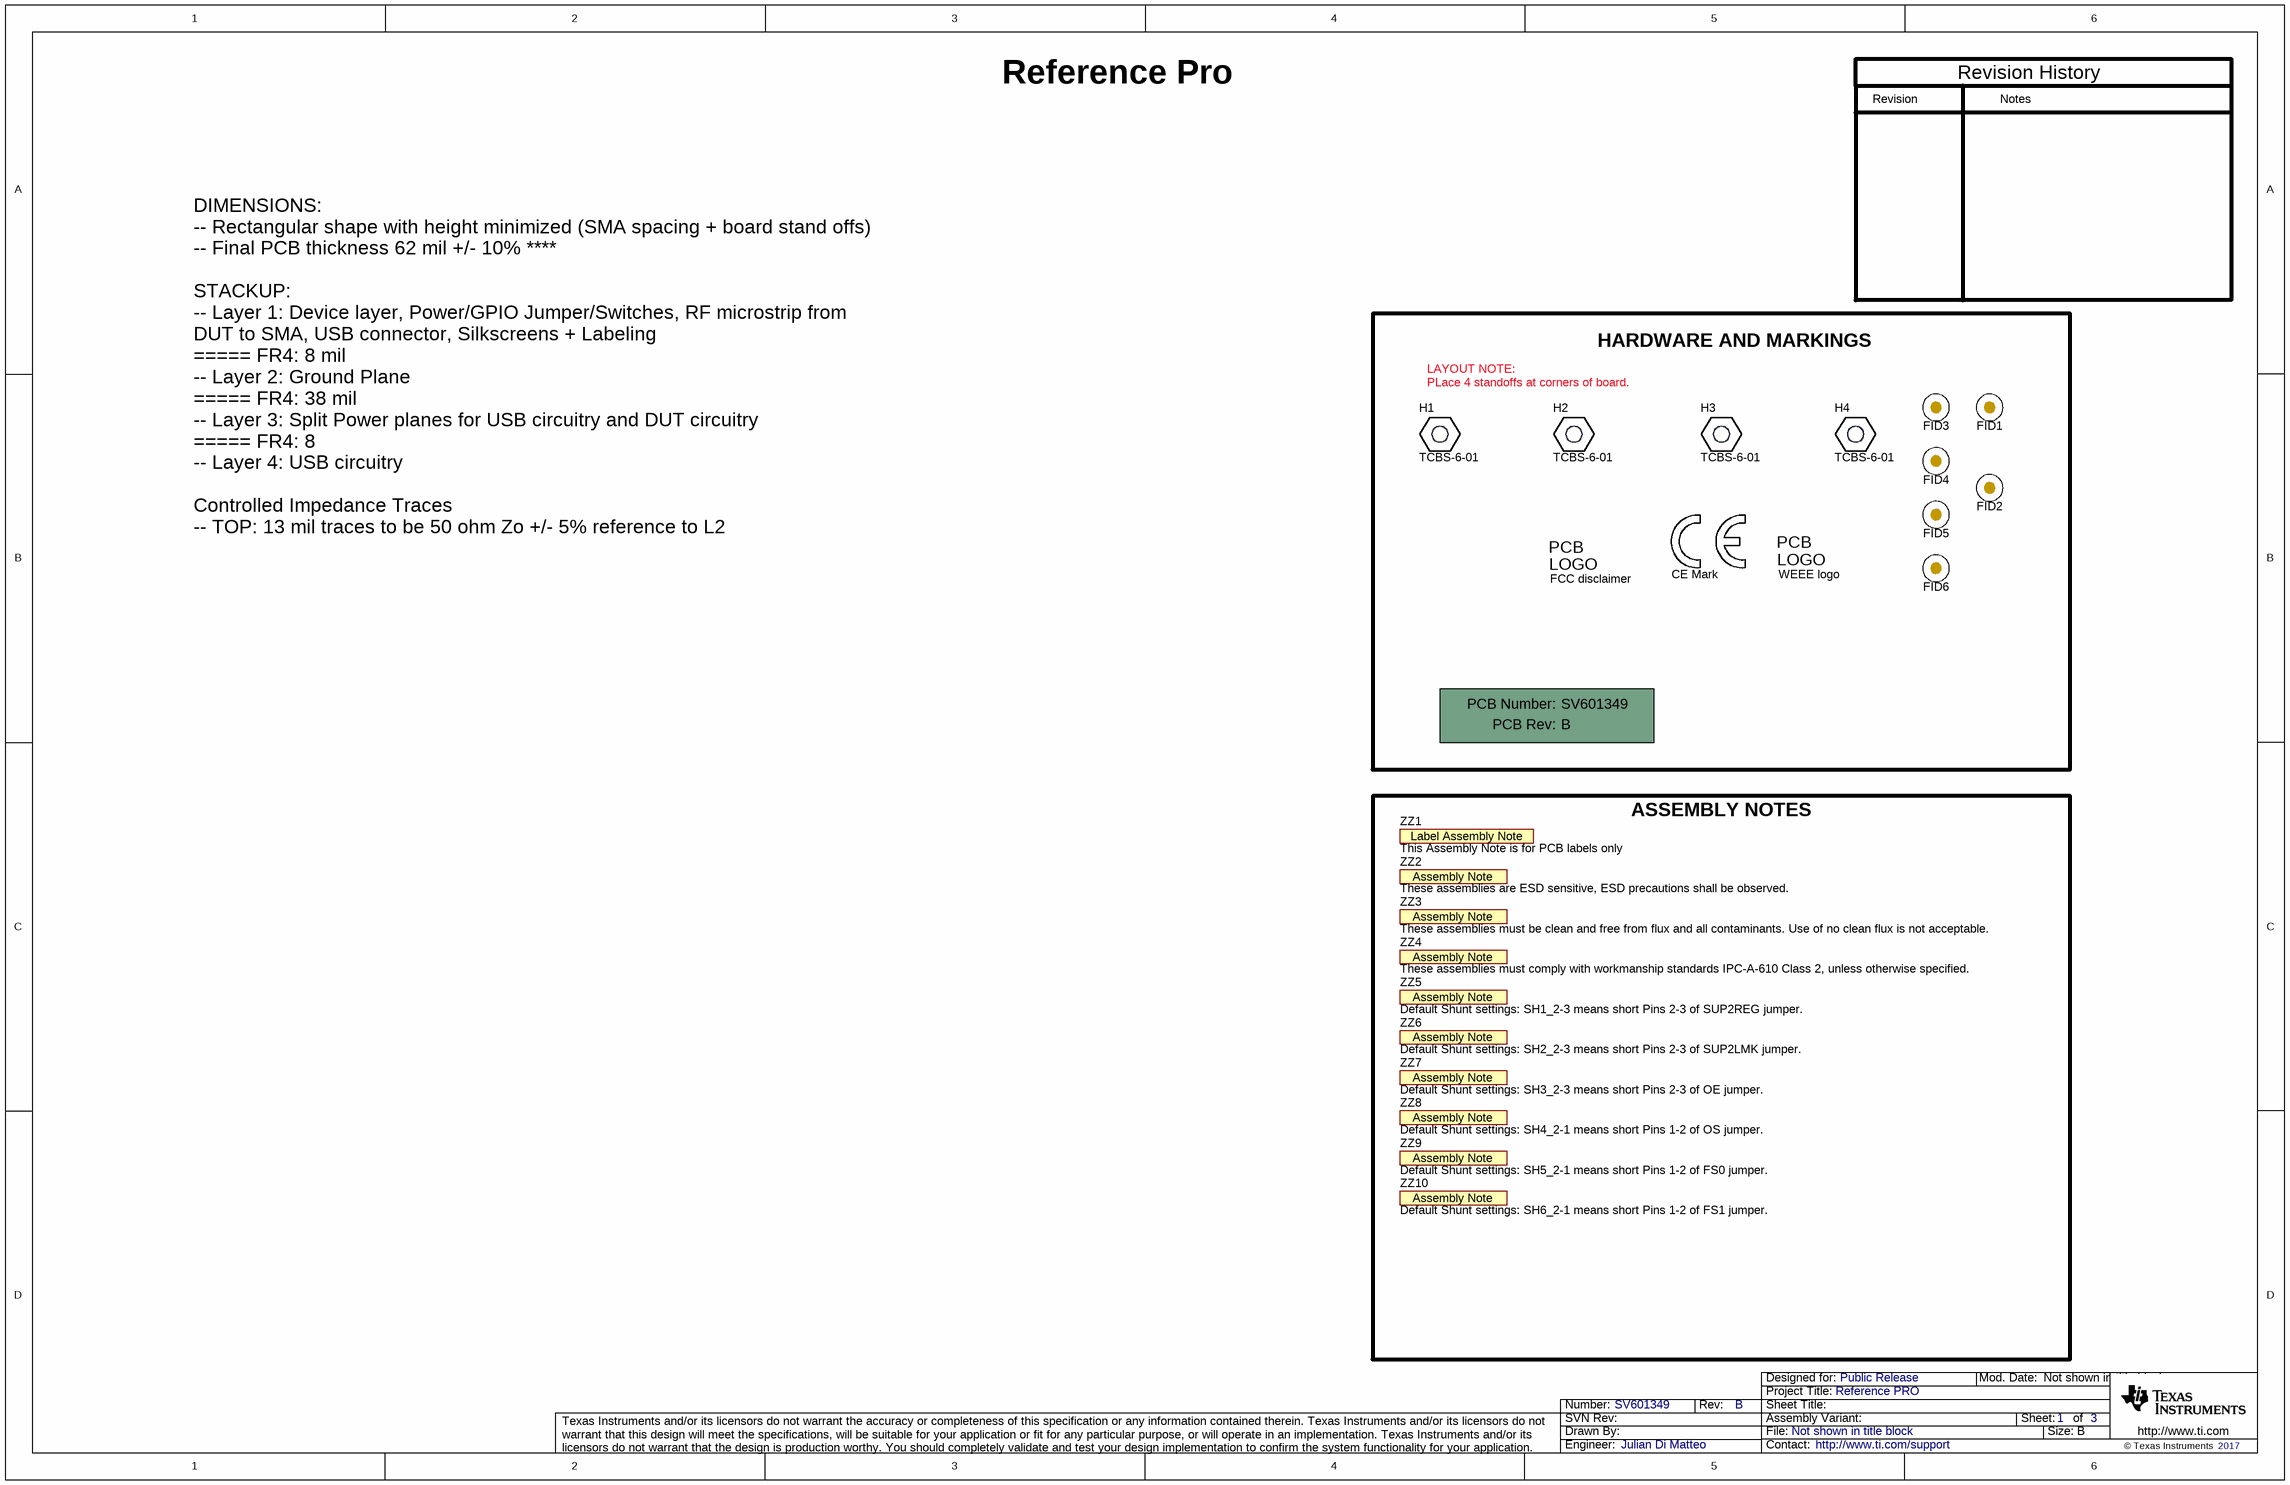
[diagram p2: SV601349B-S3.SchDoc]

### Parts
FID1  Fiducial  [Fiducial10-20]  (value not drawn)
FID2  Fiducial  [Fiducial10-20]  (value not drawn)
FID3  Fiducial  [Fiducial10-20]  (value not drawn)
FID4  Fiducial  [Fiducial10-20]  (value not drawn)
FID5  Fiducial  [Fiducial10-20]  (value not drawn)
FID6  Fiducial  [Fiducial10-20]  (value not drawn)
H1  TCBS-6-01  [TCBS-6-01]
H2  TCBS-6-01  [TCBS-6-01]
H3  TCBS-6-01  [TCBS-6-01]
H4  TCBS-6-01  [TCBS-6-01]
Logo2  WEEE logo  [WEEE_Minimum]  (no BOM)
Logo3  FCC disclaimer  [FCC_disclaimer_stacked]  (no BOM)
Logo4  CE Mark  [CE_Mark_5mm]  (no BOM)
PCB1  Printed Circuit Board  (value not drawn)  (mechanical)
ZZ1  This Assembly Note is for PCB labels only  [AssemblyNoteLabel]  (no BOM)
ZZ2  These assemblies are ESD sensitive, ESD precautions shall be observed.  [AssemblyNote]  (no BOM)
ZZ3  These assemblies must be clean and free from flux and all contaminants. Use of no clean flux is not acceptable.  [AssemblyNote]  (no BOM)
ZZ4  These assemblies must comply with workmanship standards IPC-A-610 Class 2, unless otherwise specified.  [AssemblyNote]  (no BOM)
ZZ5  Default Shunt settings: SH1_2-3 means short Pins 2-3 of SUP2REG jumper.  [AssemblyNote]  (no BOM)
ZZ6  Default Shunt settings: SH2_2-3 means short Pins 2-3 of SUP2LMK jumper.  [AssemblyNote]  (no BOM)
ZZ7  Default Shunt settings: SH3_2-3 means short Pins 2-3 of OE jumper.  [AssemblyNote]  (no BOM)
ZZ8  Default Shunt settings: SH4_2-1 means short Pins 1-2 of OS jumper.  [AssemblyNote]  (no BOM)
ZZ9  Default Shunt settings: SH5_2-1 means short Pins 1-2 of FS0 jumper.  [AssemblyNote]  (no BOM)
ZZ10  Default Shunt settings: SH6_2-1 means short Pins 1-2 of FS1 jumper.  [AssemblyNote]  (no BOM)

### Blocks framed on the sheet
HARDWARE AND MARKINGS: FID1-FID6 H1-H4 Logo2-Logo4 PCB1
ASSEMBLY NOTES: ZZ1-ZZ10

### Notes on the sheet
- Reference Pro
- Revision
- Notes
- Revision History
- LAYOUT NOTE:
  PLace 4 standoffs at corners of board.
- DIMENSIONS:
  -- Rectangular shape with height minimized (SMA spacing + board stand offs)
  -- Final PCB thickness 62 mil +/- 10% ****
  STACKUP:
  -- Layer 1: Device layer, Power/GPIO Jumper/Switches, RF microstrip from DUT to SMA, USB connector, Silkscreens + Labeling
  ===== FR4: 8 mil
  -- Layer 2: Ground Plane
  ===== FR4: 38 mil
  -- Layer 3: Split Power planes for USB circuitry and DUT circuitry
  ===== FR4: 8
  -- Layer 4: USB circuitry
  Controlled Impedance Traces
  -- TOP: 13 mil traces to be 50 ohm Zo +/- 5% reference to L2

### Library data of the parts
FID1 FID2 = Fiducial: Fiducial mark.  There is nothing to buy or mount.; SymbolCreator: codlsc
FID3-FID6 = CMP-0077181-1: Fiducial mark.  There is nothing to buy or mount.
H1-H4 = TCBS-6-01: HEX STANDOFF SPACER, 9.53 mm; Manufacturer: Richco Plastics; SymbolCreator: a0412235
Logo2 = CMP-0074769-1
Logo3 = FCC_disclaimer: SymbolCreator: codlsc
Logo4 = CMP-0074844-1: SymbolCreator: a0412235
PCB1 = PCB: Manufacturer: Any; PartNumber: SV601349; SymbolCreator: a0412235
ZZ1 = CMP-0003616-3
ZZ2 = CMP-0077236-1
ZZ3 = CMP-0077237-1
ZZ4-ZZ10 = CMP-0077238-1

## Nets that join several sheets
GND: SV601349B-S1 (44 pins), SV601349B-S2 (17 pins)
VDD: SV601349B-S1 (R8.2 SUP2LMK.2), SV601349B-S2 (7 pins)
SCL: SV601349B-S1 (J8.3 R11a.2), SV601349B-S2 (R11b.1)
SDA: SV601349B-S1 (J7.3 R9.1 R10a.2), SV601349B-S2 (R10b.1)

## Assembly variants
001: not fitted FID1 FID2 FID3 FID4 FID5 FID6 J7 J8 R10a R10b R11a R11b R12 R12a R12b R13 R13a R27 R30 SH7_2_3 SH8_2_3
